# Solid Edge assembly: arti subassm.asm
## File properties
Author: Robert a Rhodes jr
Template: Normal.asm
Last saved by: Cadcim
Revision: 17
Application: Solid Edge
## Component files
rod bush lower.par
rod bush upper.par
articulated rod.par
piston.par
piston pin.par
piston pin plug.par
piston ring.par
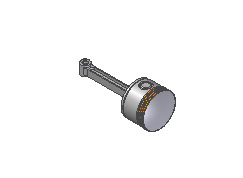
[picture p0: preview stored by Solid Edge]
